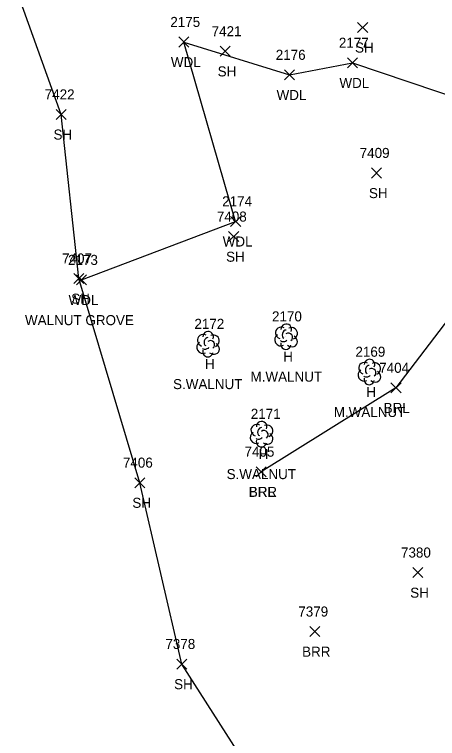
# Model space of a CAD drawing. Extents: x 1439173 to 1457902, y 641926 to 659889.
# Drawn here: x 1448534.9 to 1448619.2, y 644043.5 to 644187.7 of the extents above; entities that cross this region are included whole.
import ezdxf

# ---------------------------------------------------------------- set-up
doc = ezdxf.new("R2010")
doc.units = 0
for name, color, linetype in [('L_A', 7, 'Continuous'), ('L_C', 7, 'Continuous'), ('L_I', 7, 'Continuous'), ('L_TIC', 7, 'Continuous'), ('LABL', 7, 'Continuous'), ('LAWA', 7, 'Continuous'), ('LSOGP', 7, 'Continuous'), ('LTD', 7, 'Continuous')]:
    doc.layers.add(name, color=color, linetype=linetype)

msp = doc.modelspace()

# ---------------------------------------------------------------- linework, layer by layer
at = {"layer": 'L_TIC'}
for points in [[(1448603.26, 644184.11), (1448605.26, 644186.11)], [(1448605.26, 644184.11), (1448603.26, 644186.11)], [(1448567.63, 644181.21), (1448569.63, 644183.21)], [(1448569.63, 644181.21), (1448567.63, 644183.21)], [(1448575.88, 644179.36), (1448577.88, 644181.36)], [(1448577.88, 644179.36), (1448575.88, 644181.36)], [(1448601.22, 644177.06), (1448603.22, 644179.06)], [(1448603.22, 644177.06), (1448601.22, 644179.06)], [(1448588.69, 644174.66), (1448590.69, 644176.66)], [(1448590.69, 644174.66), (1448588.69, 644176.66)], [(1448543.18, 644166.78), (1448545.18, 644168.78)], [(1448545.18, 644166.78), (1448543.18, 644168.78)], [(1448606.02, 644155.12), (1448608.02, 644157.12)], [(1448608.02, 644155.12), (1448606.02, 644157.12)], [(1448577.96, 644145.48), (1448579.96, 644147.48)], [(1448579.96, 644145.48), (1448577.96, 644147.48)], [(1448577.56, 644142.45), (1448579.56, 644144.45)], [(1448579.56, 644142.45), (1448577.56, 644144.45)], [(1448546.72, 644134.1), (1448548.72, 644136.1)], [(1448548.72, 644134.1), (1448546.72, 644136.1)], [(1448547.25, 644133.82), (1448549.25, 644135.82)], [(1448549.25, 644133.82), (1448547.25, 644135.82)], [(1448609.9, 644112.33), (1448611.9, 644114.33)], [(1448611.9, 644112.33), (1448609.9, 644114.33)], [(1448583.06, 644095.62), (1448585.06, 644097.62)], [(1448585.06, 644095.62), (1448583.06, 644097.62)], [(1448583.06, 644095.62), (1448585.06, 644097.62)], [(1448585.06, 644095.62), (1448583.06, 644097.62)], [(1448558.89, 644093.44), (1448560.89, 644095.44)], [(1448560.89, 644093.44), (1448558.89, 644095.44)], [(1448614.24, 644075.54), (1448616.24, 644077.54)], [(1448616.24, 644075.54), (1448614.24, 644077.54)], [(1448593.71, 644063.79), (1448595.71, 644065.79)], [(1448595.71, 644063.79), (1448593.71, 644065.79)], [(1448567.22, 644057.32), (1448569.22, 644059.32)], [(1448569.22, 644057.32), (1448567.22, 644059.32)]]:
    msp.add_lwpolyline(points, dxfattribs=at)
at = {"layer": 'LABL'}
msp.add_lwpolyline([(1448618.91, 643999.04), (1448644.94, 643973.94), (1448671.1, 643946.56), (1448682.2, 643948.42), (1448702.89, 643955.83), (1448725.89, 643971.95), (1448704.02, 644009.69), (1448685.63, 644054.93), (1448678.87, 644058.56), (1448673.61, 644064.34), (1448671.51, 644072.78), (1448669.91, 644077.81), (1448660.49, 644089.37), (1448661.4, 644110.27), (1448649.96, 644144.44), (1448645.2, 644141.49), (1448627.15, 644134.63), (1448610.9, 644113.33), (1448584.06, 644096.62)], dxfattribs=at)
at = {"layer": 'LAWA'}
msp.add_lwpolyline([(1448548.25, 644134.82), (1448578.96, 644146.48), (1448568.63, 644182.21), (1448589.69, 644175.66), (1448602.22, 644178.06), (1448630.41, 644168.54), (1448628.73, 644185.43), (1448619.72, 644212.12), (1448603.69, 644230.24), (1448579.78, 644224.26), (1448558.44, 644213.23), (1448548.55, 644204.94)], dxfattribs=at)
at = {"layer": 'LSOGP'}
msp.add_lwpolyline([(1448586.99, 644029.02), (1448568.22, 644058.32), (1448559.89, 644094.44), (1448547.72, 644135.1), (1448544.18, 644167.78), (1448534.9, 644193.73)], dxfattribs=at)
at = {"layer": 'LTD'}
for p, q in [((1448588.98, 644123.57), (1448588.98, 644123.57)), ((1448588.98, 644123.57), (1448588.98, 644123.57)), ((1448573.43, 644122.08), (1448573.43, 644122.08)), ((1448573.43, 644122.08), (1448573.43, 644122.08)), ((1448605.57, 644116.53), (1448605.57, 644116.53)), ((1448605.57, 644116.53), (1448605.57, 644116.53)), ((1448584.1, 644104.16), (1448584.1, 644104.16)), ((1448584.1, 644104.16), (1448584.1, 644104.16))]:
    msp.add_line(p, q, dxfattribs=at)
for centre in [(1448589.03, 644125), (1448573.48, 644123.52), (1448605.62, 644117.97), (1448584.14, 644105.6)]:
    msp.add_arc(centre, 1.05, 335.5272, 180.9563, dxfattribs=at)
for centre, major_axis, ratio, start_param, end_param in [((1448588.19, 644124.23), (1.21, -0.51), 0.895232, 1.570796, 4.712389), ((1448590.03, 644124.15), (-1.14, -0.48), 0.949671, 1.570796, 4.712389), ((1448572.64, 644122.75), (1.21, -0.51), 0.895232, 1.570796, 4.712389), ((1448588.78, 644124.03), (-0.208, -0.792), 0.645439, 3.141593, 6.283185), ((1448589.48, 644123.4), (-0.5, 0.667), 0.989748, 3.141593, 6.283185), ((1448573.22, 644122.54), (-0.208, -0.792), 0.645439, 3.141593, 6.283185), ((1448573.93, 644121.92), (-0.5, 0.667), 0.989748, 3.141593, 6.283185), ((1448574.47, 644122.67), (-1.14, -0.48), 0.949671, 1.570796, 4.712389), ((1448587.9, 644122.86), (0.58, -1.04), 0.959034, 3.141593, 6.283185), ((1448588.53, 644122.82), (-0.625, -0.083), 0.423636, 0, 3.141593), ((1448589.98, 644122.73), (-1.09, 0.79), 0.841452, 1.570796, 4.712389), ((1448572.35, 644121.37), (0.58, -1.04), 0.959034, 3.141593, 6.283185), ((1448572.97, 644121.33), (-0.625, -0.083), 0.423636, 0, 3.141593), ((1448574.43, 644121.25), (-1.09, 0.79), 0.841452, 1.570796, 4.712389), ((1448588.98, 644122.07), (0.26, 1.06), 0.942809, 1.570796, 4.712389), ((1448573.43, 644120.58), (0.26, 1.06), 0.942809, 1.570796, 4.712389), ((1448604.78, 644117.2), (1.21, -0.51), 0.895232, 1.570796, 4.712389), ((1448606.61, 644117.12), (-1.14, -0.48), 0.949671, 1.570796, 4.712389), ((1448604.49, 644115.83), (0.58, -1.04), 0.959034, 3.141593, 6.283185), ((1448605.36, 644116.99), (-0.208, -0.792), 0.645439, 3.141593, 6.283185), ((1448606.07, 644116.37), (-0.5, 0.667), 0.989748, 3.141593, 6.283185), ((1448605.11, 644115.78), (-0.625, -0.083), 0.423636, 0, 3.141593), ((1448606.57, 644115.7), (-1.09, 0.79), 0.841452, 1.570796, 4.712389), ((1448605.57, 644115.03), (0.26, 1.06), 0.942809, 1.570796, 4.712389), ((1448583.3, 644104.83), (1.21, -0.51), 0.895232, 1.570796, 4.712389), ((1448583.89, 644104.62), (-0.208, -0.792), 0.645439, 3.141593, 6.283185), ((1448585.14, 644104.75), (-1.14, -0.48), 0.949671, 1.570796, 4.712389), ((1448583.01, 644103.45), (0.58, -1.04), 0.959034, 3.141593, 6.283185), ((1448584.6, 644104), (-0.5, 0.667), 0.989748, 3.141593, 6.283185), ((1448585.1, 644103.33), (-1.09, 0.79), 0.841452, 1.570796, 4.712389), ((1448584.1, 644102.66), (0.26, 1.06), 0.942809, 1.570796, 4.712389), ((1448583.64, 644103.41), (-0.625, -0.083), 0.423636, 0, 3.141593)]:
    msp.add_ellipse(centre, major_axis=major_axis, ratio=ratio, start_param=start_param, end_param=end_param, dxfattribs=at)

# ---------------------------------------------------------------- texts
at = {"layer": 'L_A'}
for s, p in [('SH', (1448602.75, 644180.11)), ('WDL', (1448566.05, 644177.21)), ('SH', (1448575.37, 644175.36)), ('WDL', (1448599.63, 644173.06)), ('WDL', (1448587.11, 644170.66)), ('SH', (1448542.67, 644162.78)), ('SH', (1448605.51, 644151.12)), ('WDL', (1448576.38, 644141.48)), ('SH', (1448577.05, 644138.45)), ('WDL', (1448545.67, 644129.82)), ('SH', (1448546.2, 644130.1)), ('H', (1448588.42, 644118.57)), ('H', (1448572.86, 644117.08)), ('H', (1448605, 644111.53)), ('BRL', (1448608.44, 644108.33)), ('H', (1448583.53, 644099.16)), ('BRR', (1448581.55, 644091.62)), ('BRL', (1448581.6, 644091.62)), ('SH', (1448558.38, 644089.44)), ('SH', (1448613.73, 644071.54)), ('BRR', (1448592.2, 644059.79)), ('SH', (1448566.7, 644053.32))]:
    msp.add_text(s, height=2, dxfattribs=at).set_placement(p)
at = {"layer": 'L_C'}
for s, p in [('WALNUT GROVE', (1448536.99, 644125.82)), ('M.WALNUT', (1448581.92, 644114.57)), ('S.WALNUT', (1448566.49, 644113.08)), ('M.WALNUT', (1448598.51, 644107.53)), ('S.WALNUT', (1448577.16, 644095.16))]:
    msp.add_text(s, height=2, dxfattribs=at).set_placement(p)
at = {"layer": 'L_I'}
for s, p in [('2175', (1448565.94, 644185.21)), ('7421', (1448574.18, 644183.36)), ('2177', (1448599.52, 644181.06)), ('2176', (1448586.95, 644178.66)), ('7422', (1448540.92, 644170.78)), ('7409', (1448603.67, 644159.12)), ('2174', (1448576.27, 644149.48)), ('7408', (1448575.22, 644146.45)), ('7407', (1448544.38, 644138.1)), ('2173', (1448545.56, 644137.82)), ('2170', (1448586.2, 644126.57)), ('2172', (1448570.74, 644125.08)), ('2169', (1448602.82, 644119.53)), ('7404', (1448607.56, 644116.33)), ('2171', (1448581.97, 644107.16)), ('7405', (1448580.72, 644099.62)), ('7405', (1448580.72, 644099.62)), ('7406', (1448556.5, 644097.44)), ('7380', (1448611.9, 644079.54)), ('7379', (1448591.44, 644067.79)), ('7378', (1448564.96, 644061.32))]:
    msp.add_text(s, height=2, dxfattribs=at).set_placement(p)

doc.saveas('drawing.dxf')
